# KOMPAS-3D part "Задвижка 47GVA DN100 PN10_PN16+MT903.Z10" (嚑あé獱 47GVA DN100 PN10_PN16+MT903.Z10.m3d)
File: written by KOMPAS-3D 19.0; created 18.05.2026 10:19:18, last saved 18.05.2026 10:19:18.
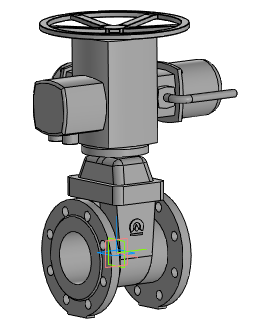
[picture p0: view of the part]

Document properties: Автор: Энергия; Полное имя файла: ..\Задвижка 47GVA DN50_DN1000+MT903.Z\Задвижка 47GVA DN100 PN10_PN16+MT903.Z10.a3d

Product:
- Part/product: Задвижка 47GVA DN100 PN10_PN16+MT903.Z10
    Масса: 78.9634
  - Body: Электропривод MT903.Z05-15
      Масса: 49.8062
  - Body: Задвижка 47GVA DN100 PN10_PN16 без исполнит. мех.
      Масса: 29.1572

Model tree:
1. Операция без истории:1
2. Операция без истории:2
